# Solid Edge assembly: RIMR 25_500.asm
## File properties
Title: Zylinder
Author: ahadarics
Template: iso metric assembly.asm
Last saved by: ahadarics
Revision: 19
Application: Solid Edge
Username: ahadarics
Dokumentum tartalom típus: 1
Document Number: RIMR 25/500
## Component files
Profilrohr.par
Kolbenstange.par
Kit_1.par
Kit_2.par
Mutter_1.par
Mutter_2.par
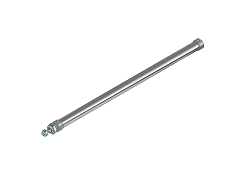
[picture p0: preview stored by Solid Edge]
